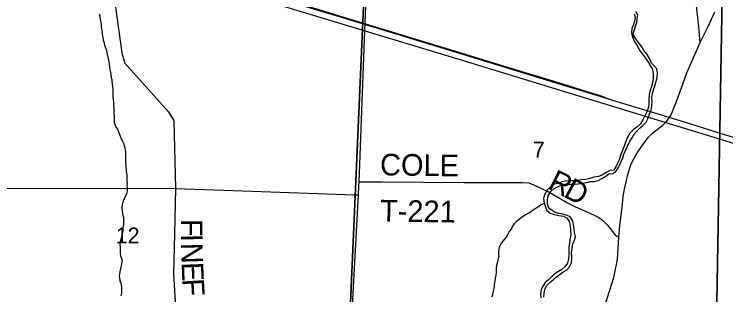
# Model space of a CAD drawing. Extents: x 0 to 34, y 0 to 22.
# Drawn here: x 25.144 to 27.011, y 18.136 to 18.872 of the extents above; entities that cross this region are included whole.
import ezdxf

# ---------------------------------------------------------------- set-up
doc = ezdxf.new("R2010")
doc.units = 0
for name, color, linetype in [('GM_X_County_Road', 7, 'Continuous'), ('GM_X_County_Road_Text', 7, 'Continuous'), ('GM_X_Minor_River', 7, 'Continuous'), ('GM_X_Rail_Line', 7, 'Continuous'), ('GM_X_Section', 7, 'Continuous'), ('GM_X_Section_Text', 7, 'Continuous'), ('GM_X_State_Route', 7, 'Continuous'), ('GM_X_Township_Road', 7, 'Continuous'), ('GM_X_Township_Road_Text', 7, 'Continuous')]:
    doc.layers.add(name, color=color, linetype=linetype)

msp = doc.modelspace()

# ---------------------------------------------------------------- linework, layer by layer
at = {"layer": 'GM_X_County_Road'}
for p, q in [((26.0643, 18.8283), (26.0866, 19.4072)), ((26.0491, 18.4323), (26.0643, 18.8283)), ((26.0471, 18.3979), (26.0484, 18.4209)), ((26.0484, 18.4209), (26.0491, 18.4323)), ((26.0016, 17.5418), (26.0471, 18.3979))]:
    msp.add_line(p, q, dxfattribs=at)
for points in [[(25.3738, 19.0391), (25.3876, 19.0014), (25.4057, 18.9229), (25.4261, 18.7706), (25.4348, 18.7435), (25.5481, 18.6163), (25.5629, 18.5929), (25.567, 18.4152)], [(25.567, 18.4152), (25.5646, 18.2951), (25.5618, 18.1907), (25.5686, 18.0751), (25.5717, 18.0261), (25.5819, 17.9792), (25.7259, 17.7714), (25.8295, 17.6782), (26.0016, 17.5418)]]:
    msp.add_lwpolyline(points, dxfattribs=at)
at = {"layer": 'GM_X_Minor_River'}
for points in [[(25.3674, 18.8731), (25.3685, 18.8682), (25.3692, 18.8632), (25.3699, 18.8587), (25.3706, 18.8545), (25.3713, 18.8499), (25.372, 18.8446), (25.3727, 18.8397), (25.373, 18.8328), (25.3745, 18.8245), (25.3752, 18.8195), (25.3759, 18.815), (25.3776, 18.8032), (25.3802, 18.7967), (25.3813, 18.7906), (25.3835, 18.7838), (25.3861, 18.7765), (25.3871, 18.7708), (25.3882, 18.7662), (25.39, 18.759), (25.3911, 18.751), (25.3929, 18.7427), (25.3939, 18.7324), (25.395, 18.7263), (25.3964, 18.7191), (25.3981, 18.7058), (25.4, 18.7004), (25.4007, 18.6959), (25.4014, 18.6879), (25.4021, 18.6826), (25.4027, 18.6761), (25.403, 18.6678), (25.4033, 18.6613)], [(26.6139, 18.2994), (26.6127, 18.31), (26.6114, 18.3196), (26.6095, 18.3302), (26.6025, 18.3403), (26.5924, 18.3448), (26.5834, 18.3477), (26.5724, 18.3491), (26.563, 18.3516), (26.5556, 18.3575), (26.5463, 18.3635), (26.5431, 18.3735), (26.543, 18.3829), (26.544, 18.3936), (26.552, 18.407), (26.5606, 18.4151), (26.5706, 18.4202), (26.5798, 18.4237), (26.5897, 18.4253), (26.6029, 18.4261), (26.6136, 18.4262), (26.6235, 18.4271), (26.6341, 18.429), (26.6459, 18.4306), (26.6551, 18.433), (26.665, 18.4335), (26.6756, 18.4359), (26.6856, 18.4413), (26.6961, 18.4475), (26.7042, 18.4529), (26.7144, 18.4542), (26.7225, 18.4596), (26.7296, 18.4697), (26.7337, 18.4798), (26.7402, 18.4956), (26.7431, 18.505), (26.7487, 18.5163), (26.7532, 18.526), (26.7592, 18.5391), (26.7655, 18.5473), (26.7707, 18.5574), (26.7785, 18.5659), (26.7859, 18.5737), (26.7933, 18.5803), (26.8015, 18.5888), (26.8059, 18.5978), (26.8104, 18.6095), (26.8153, 18.6204), (26.8163, 18.6306), (26.8174, 18.6427), (26.8165, 18.6537), (26.8187, 18.6635), (26.8217, 18.676), (26.8254, 18.6865), (26.8283, 18.6963), (26.8305, 18.7057), (26.8315, 18.7171), (26.83, 18.7289), (26.8226, 18.7363), (26.8159, 18.7434), (26.8109, 18.7553), (26.8044, 18.7657), (26.7956, 18.7766), (26.7902, 18.7858), (26.7839, 18.794), (26.7777, 18.8033), (26.7711, 18.8114), (26.7676, 18.821), (26.7709, 18.8304), (26.7742, 18.8402), (26.7771, 18.85), (26.7781, 18.8598), (26.7799, 18.87), (26.7749, 18.8789)], [(26.7705, 18.8729), (26.7725, 18.8634), (26.7715, 18.8535), (26.7682, 18.8445), (26.7645, 18.834), (26.7631, 18.8223), (26.7665, 18.8096), (26.7716, 18.7996), (26.7774, 18.7911), (26.7828, 18.78), (26.7886, 18.7714), (26.7956, 18.7625), (26.8014, 18.7536), (26.8076, 18.7451), (26.8131, 18.7358), (26.8185, 18.7266), (26.8205, 18.7155), (26.8205, 18.703), (26.818, 18.692), (26.8162, 18.6822), (26.8121, 18.6725), (26.8095, 18.6608), (26.8088, 18.6483), (26.8089, 18.6365), (26.8079, 18.627), (26.8038, 18.6157), (26.7985, 18.6053), (26.7929, 18.5944), (26.7866, 18.5847), (26.7769, 18.5755), (26.768, 18.5689), (26.7586, 18.56), (26.7522, 18.5477), (26.7474, 18.5364), (26.7444, 18.5255), (26.7391, 18.5123), (26.7343, 18.5015), (26.7306, 18.4898), (26.7262, 18.4812), (26.7225, 18.4718)], [(25.4033, 18.6613), (25.4033, 18.6571), (25.4035, 18.6469), (25.4042, 18.6412), (25.4045, 18.6309), (25.4056, 18.6245), (25.4055, 18.6192), (25.4058, 18.6116), (25.4061, 18.6062), (25.406, 18.5975), (25.406, 18.5933), (25.4067, 18.588), (25.4078, 18.5838), (25.41, 18.5774), (25.4148, 18.5701), (25.4174, 18.5629), (25.4233, 18.5506), (25.4251, 18.5453), (25.4277, 18.5403), (25.4307, 18.5339), (25.4329, 18.5274), (25.434, 18.5213), (25.4354, 18.516), (25.4365, 18.5107), (25.4363, 18.4898), (25.4358, 18.4848), (25.4369, 18.4761), (25.4372, 18.4708), (25.4375, 18.464), (25.4378, 18.4598), (25.4389, 18.4556), (25.4392, 18.4495), (25.4395, 18.4431), (25.4398, 18.4328), (25.4401, 18.4267), (25.44, 18.4218), (25.4408, 18.4176), (25.4407, 18.4131), (25.4403, 18.4081), (25.4387, 18.4009), (25.4348, 18.3915), (25.432, 18.3858), (25.4289, 18.3786), (25.4277, 18.3722), (25.4265, 18.3665), (25.4268, 18.3608), (25.4286, 18.3498), (25.4293, 18.3449), (25.4311, 18.3384), (25.4311, 18.3327), (25.4305, 18.3209), (25.4293, 18.3096), (25.4288, 18.3039), (25.4264, 18.294), (25.4252, 18.2872), (25.424, 18.2819), (25.422, 18.274), (25.4216, 18.2698), (25.4219, 18.2614), (25.4219, 18.2573), (25.4221, 18.2489), (25.4221, 18.244), (25.4228, 18.2383), (25.425, 18.2337), (25.4261, 18.2295), (25.4264, 18.2219), (25.4251, 18.2132), (25.422, 18.2011), (25.4212, 18.1962), (25.4207, 18.1901), (25.4199, 18.1852), (25.4202, 18.1806), (25.4216, 18.1726), (25.4235, 18.1669), (25.4246, 18.162), (25.4252, 18.154), (25.4259, 18.1449), (25.4255, 18.1407), (25.4239, 18.1335)], [(26.7225, 18.4718), (26.717, 18.4632), (26.7071, 18.4623), (26.6971, 18.4565), (26.6882, 18.4507), (26.6767, 18.4465), (26.6641, 18.4442), (26.6538, 18.4407), (26.6435, 18.4383), (26.6321, 18.4371), (26.621, 18.4355), (26.6115, 18.4346), (26.6017, 18.4345), (26.5903, 18.4344), (26.5807, 18.4324), (26.5711, 18.4281), (26.5609, 18.4265), (26.5516, 18.4203), (26.5427, 18.4122), (26.5363, 18.4002), (26.5325, 18.3886), (26.5341, 18.3767), (26.5376, 18.3668), (26.5416, 18.3575), (26.5501, 18.3497), (26.561, 18.3464), (26.5723, 18.3438), (26.5851, 18.3419), (26.5945, 18.3371), (26.5999, 18.3286), (26.6026, 18.3168), (26.6035, 18.3054), (26.6039, 18.2936), (26.6017, 18.2811), (26.601, 18.2716), (26.5992, 18.2611), (26.5993, 18.25), (26.599, 18.2402), (26.5984, 18.2303), (26.5951, 18.2186), (26.5884, 18.2097), (26.5802, 18.2027), (26.5702, 18.1962), (26.5598, 18.1896), (26.5527, 18.1826), (26.5453, 18.1752), (26.5372, 18.1682), (26.5309, 18.1585), (26.5264, 18.1495), (26.525, 18.1382), (26.5259, 18.1279)], [(26.5346, 18.3752), (26.5251, 18.3722), (26.5205, 18.3673), (26.5121, 18.3621), (26.5056, 18.3576), (26.4957, 18.3513), (26.4854, 18.3457), (26.4743, 18.3375), (26.4605, 18.327), (26.4555, 18.3221), (26.4493, 18.3138), (26.4485, 18.3093), (26.4424, 18.3021), (26.44, 18.2965), (26.437, 18.2916), (26.4342, 18.287), (26.4289, 18.281), (26.4219, 18.2727), (26.4165, 18.2614), (26.4157, 18.2542), (26.4149, 18.2497), (26.4148, 18.2413), (26.4151, 18.2367), (26.4127, 18.2277), (26.4119, 18.2224), (26.4091, 18.2133), (26.4087, 18.2057), (26.4082, 18.1951), (26.4073, 18.1875), (26.4057, 18.1795), (26.4049, 18.172), (26.4029, 18.1629), (26.4028, 18.1568), (26.4016, 18.1492), (26.4, 18.1424), (26.3984, 18.1363), (26.3957, 18.1303)], [(26.5335, 18.13), (26.5342, 18.1406), (26.5356, 18.1512), (26.5411, 18.1605), (26.5497, 18.169), (26.5583, 18.1764), (26.5668, 18.183), (26.5765, 18.1903), (26.5842, 18.1962), (26.5938, 18.2016), (26.6005, 18.209), (26.6057, 18.2202), (26.6065, 18.2335), (26.6061, 18.2468), (26.6075, 18.257), (26.6093, 18.2695), (26.6134, 18.2796), (26.6163, 18.2887), (26.6139, 18.2994)]]:
    msp.add_lwpolyline(points, dxfattribs=at)
at = {"layer": 'GM_X_Rail_Line'}
for points in [[(24.1704, 19.5327), (24.2425, 19.4909), (24.3878, 19.4135), (24.5787, 19.3195), (24.7175, 19.2589), (24.8405, 19.2105), (24.9746, 19.1639), (25.4423, 19.0168), (26.3104, 18.7542), (27.1506, 18.4971), (27.9899, 18.2401), (28.4862, 18.088)], [(25.1011, 19.1396), (25.1536, 19.1235), (25.2694, 19.0879), (25.2996, 19.0787), (25.3683, 19.0577), (25.4595, 19.0299), (25.6015, 18.9867), (25.8055, 18.9242), (25.847, 18.9114), (25.9704, 18.8734), (26.0653, 18.8446), (26.2947, 18.7744), (26.4597, 18.7238), (26.5651, 18.6918), (26.6458, 18.6671), (26.7252, 18.6428), (26.8299, 18.611), (26.9128, 18.5857), (26.9875, 18.5627), (27.1965, 18.4991)], [(25.4438, 19.0347), (25.4601, 19.0321), (25.6021, 18.989), (25.8062, 18.9265), (25.8477, 18.9137), (25.9711, 18.8756), (26.066, 18.8468), (26.2954, 18.7766), (26.4604, 18.726), (26.5658, 18.694), (26.6465, 18.6693), (26.6813, 18.6587), (26.7055, 18.6488)]]:
    msp.add_lwpolyline(points, dxfattribs=at)
at = {"layer": 'GM_X_Section'}
for points in [[(26.0607, 18.8928), (26.0171, 17.9156), (26.0158, 17.891), (24.9267, 17.9117), (24.9624, 18.9716)], [(27.0012, 18.9192), (26.984, 17.9172), (26.0171, 17.9156), (26.0607, 18.8928), (26.0616, 18.9227)], [(28.001, 18.9217), (27.9928, 17.9132), (26.984, 17.9172), (27.0012, 18.9192)]]:
    msp.add_lwpolyline(points, close=True, dxfattribs=at)
at = {"layer": 'GM_X_State_Route'}
for points in [[(26.73, 18.2876), (26.7328, 18.3167), (26.7393, 18.374), (26.7418, 18.3947), (26.7449, 18.4126), (26.749, 18.432), (26.7527, 18.4479), (26.7551, 18.4569), (26.7587, 18.4685), (26.7628, 18.4792), (26.7691, 18.4928), (26.7784, 18.5083), (26.7902, 18.5255), (26.799, 18.5376), (26.808, 18.5492), (26.8176, 18.5586), (26.8275, 18.5672), (26.8459, 18.581), (26.8544, 18.5898), (26.8608, 18.5972), (26.8661, 18.6063), (26.8728, 18.6212), (26.8797, 18.6385), (26.8941, 18.6783), (26.9086, 18.7181), (26.9206, 18.746), (26.9438, 18.7976), (26.9651, 18.8414), (26.9822, 18.8778)], [(26.6874, 18.0883), (26.7172, 18.1813), (26.7264, 18.2283), (26.73, 18.2876)]]:
    msp.add_lwpolyline(points, dxfattribs=at)
at = {"layer": 'GM_X_Township_Road'}
for p, q in [((26.0471, 18.3979), (26.0484, 18.4209)), ((26.0484, 18.4209), (26.0491, 18.4323))]:
    msp.add_line(p, q, dxfattribs=at)
for points in [[(26.9438, 18.7976), (26.9401, 18.8386), (26.933, 18.9019), (26.9318, 18.9164), (26.9321, 18.9296), (26.9332, 18.9447), (26.9348, 18.9571), (26.938, 18.9733), (26.9426, 18.9888), (26.9445, 18.9983), (26.9455, 19.0107), (26.946, 19.0253), (26.9461, 19.0601), (26.9472, 19.0885), (26.9477, 19.0971)], [(26.0491, 18.4323), (26.1093, 18.4319), (26.3243, 18.4309), (26.4529, 18.4304), (26.4759, 18.4306), (26.494, 18.4292), (26.5201, 18.4185), (26.5258, 18.4158)], [(24.9527, 18.4155), (24.9558, 18.4155), (25.567, 18.4152)], [(25.567, 18.4152), (25.7181, 18.4093), (26.0379, 18.3982), (26.0471, 18.3979)], [(26.5258, 18.4158), (26.5477, 18.4055), (26.5744, 18.389), (26.5951, 18.3775), (26.6163, 18.3668), (26.6351, 18.3587), (26.6654, 18.3451), (26.6775, 18.3384), (26.6872, 18.3317), (26.6946, 18.3252), (26.7016, 18.3175), (26.7136, 18.3019), (26.7184, 18.2952), (26.7217, 18.2919), (26.73, 18.2876)]]:
    msp.add_lwpolyline(points, dxfattribs=at)

# ---------------------------------------------------------------- texts
at = {"layer": 'GM_X_County_Road_Text'}
for s, rotation, p in [('F', 269.7814, (25.5813, 18.3353)), ('I', 271.4097, (25.5812, 18.2952)), ('N', 271.524, (25.5818, 18.2717)), ('E', 272.3129, (25.5831, 18.2209)), ('F', 273.2027, (25.5849, 18.1774))]:
    msp.add_text(s, height=0.0568, rotation=rotation, dxfattribs=at).set_placement(p)
at = {"layer": 'GM_X_Section_Text'}
for s, height, p in [('7', 0.0419, (26.5044, 18.4955)), ('12', 0.04186, (25.4107, 18.2707))]:
    msp.add_text(s, height=height, rotation=0, dxfattribs=at).set_placement(p)
at = {"layer": 'GM_X_Township_Road_Text'}
for s, height, rotation, p in [('COLE', 0.05682, 359.2115, (26.1035, 18.4493)), ('R', 0.0568, 333.6793, (26.541, 18.4155)), ('D', 0.0568, 331.1796, (26.5823, 18.3951)), ('T-221', 0.05682, 359.1574, (26.1034, 18.3284))]:
    msp.add_text(s, height=height, rotation=rotation, dxfattribs=at).set_placement(p)

doc.saveas('drawing.dxf')
